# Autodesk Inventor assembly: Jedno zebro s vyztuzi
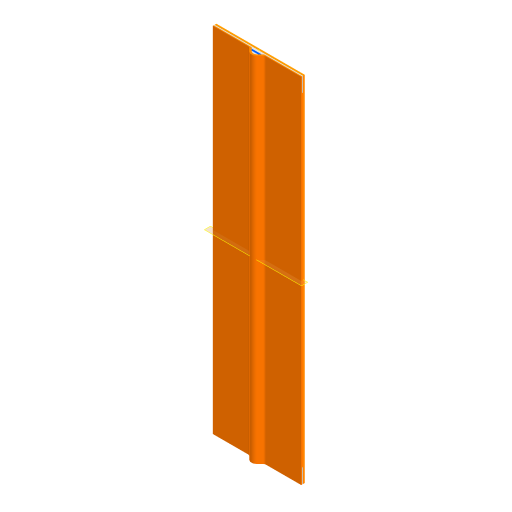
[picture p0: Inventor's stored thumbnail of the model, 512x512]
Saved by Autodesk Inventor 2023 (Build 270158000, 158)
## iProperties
Created: 2025-03
Part Number: Jedno zebro s vyztuzi
Document SubType Name: Assembly
Designer: tomik
Author: tomik
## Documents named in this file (5)
- C:\Users\tomik\Desktop\Diplomka\Struktury\Desky\Struktury_20.3\Jedno žebro s výztuží\Jedno zebro s vyztuzi.iam
- C:\Users\tomik\Desktop\Diplomka\Struktury\Desky\Struktury_20.3\Jedno žebro s výztuží\Zebro s vyztuhou.ipt
- C:\Users\tomik\Desktop\Diplomka\Struktury\Desky\Struktury_20.3\Jedno žebro s výztuží\Vyztuha.ipt
- C:\Users\tomik\Desktop\Diplomka\Struktury\Desky\Struktury_20.3\Jedno žebro s výztuží\Spodni tkanina 50x200.ipt
- C:\Users\tomik\Desktop\Diplomka\Struktury\Desky\Struktury_20.3\Jedno žebro s výztuží\Horni tkanina.ipt
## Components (4 placed, 4 different names)
1. Zebro s vyztuhou:1 — Proti sobě:1, Proti sobě:2, Stejný směr:1, Proti sobě:3, Proti sobě:4, Proti sobě:5, Proti sobě:6, Stejný směr:2, Proti sobě:7
2. Vyztuha:1 — Proti sobě:3, Proti sobě:4, Proti sobě:5
3. Spodni tkanina 50x200:1 — Proti sobě:6, Stejný směr:2, Proti sobě:7, Proti sobě:8, Stejný směr:3, Stejný směr:4
4. Horni tkanina:1 — Proti sobě:8, Stejný směr:3, Stejný směr:4
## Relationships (12: Mate 8, Flush 4)
- Proti sobě:1 [Mate]: Zebro s vyztuhou:1
- Proti sobě:2 [Mate]: Zebro s vyztuhou:1
- Stejný směr:1 [Flush]: Zebro s vyztuhou:1
- Proti sobě:3 [Mate]: Zebro s vyztuhou:1 ↔ Vyztuha:1
- Proti sobě:4 [Mate]: Zebro s vyztuhou:1 ↔ Vyztuha:1
- Proti sobě:5 [Mate]: Zebro s vyztuhou:1 ↔ Vyztuha:1
- Proti sobě:6 [Mate]: Zebro s vyztuhou:1 ↔ Spodni tkanina 50x200:1
- Stejný směr:2 [Flush]: Zebro s vyztuhou:1 ↔ Spodni tkanina 50x200:1
- Proti sobě:7 [Mate]: Zebro s vyztuhou:1 ↔ Spodni tkanina 50x200:1
- Proti sobě:8 [Mate]: Spodni tkanina 50x200:1 ↔ Horni tkanina:1
- Stejný směr:3 [Flush]: Spodni tkanina 50x200:1 ↔ Horni tkanina:1
- Stejný směr:4 [Flush]: Spodni tkanina 50x200:1 ↔ Horni tkanina:1
